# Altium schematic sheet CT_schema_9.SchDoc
size 274 x 160 mm
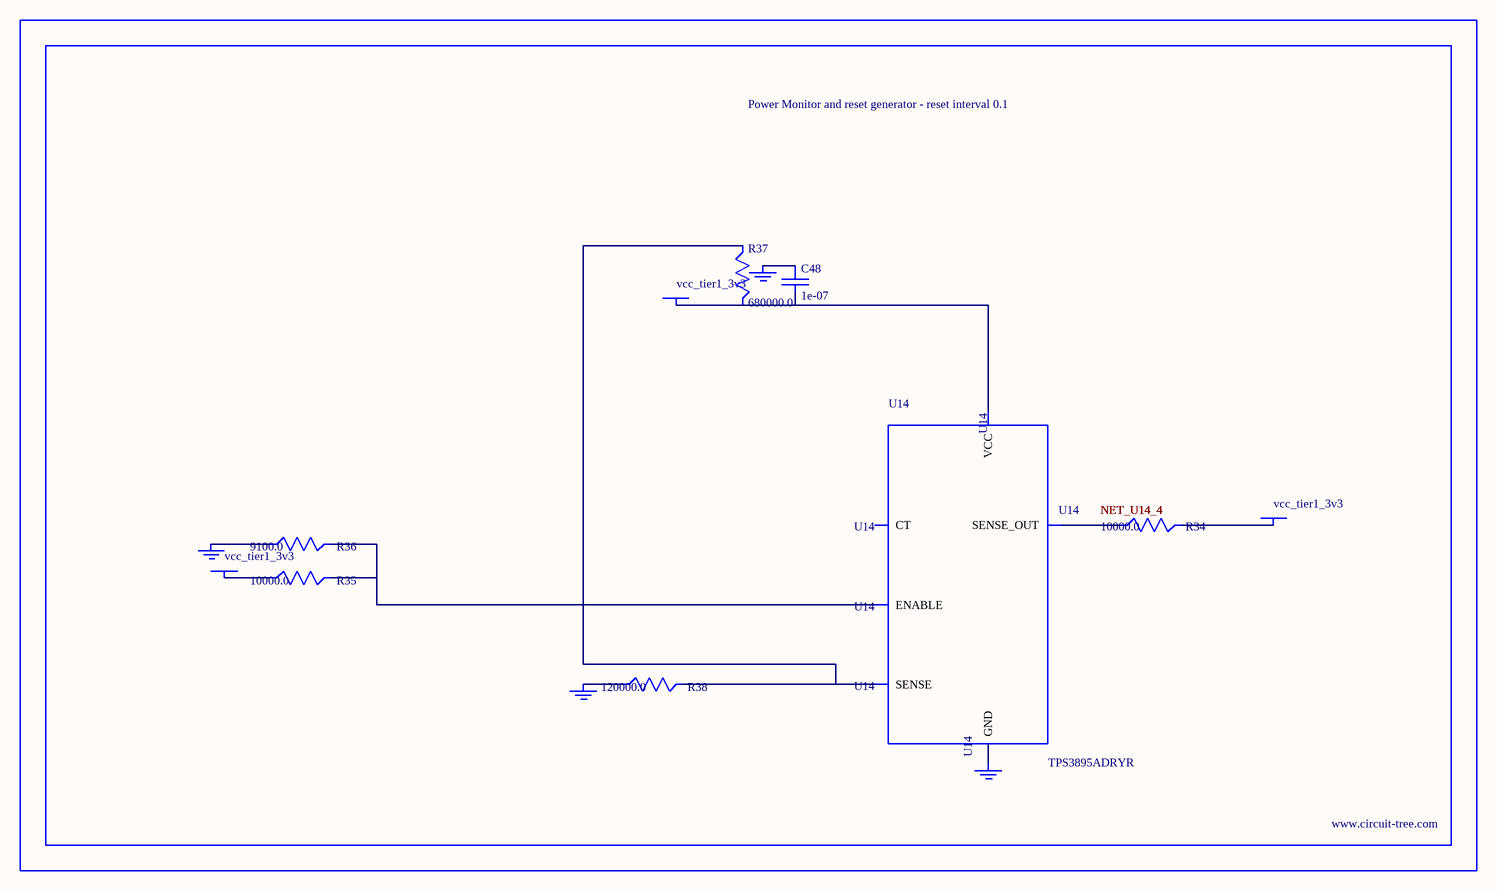
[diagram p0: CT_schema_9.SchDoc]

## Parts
BORDER8  (no value)
C48  1e-07  [C0402]
GND_INSTANCE_8_0  (no value)
GND_INSTANCE_8_1  (no value)
GND_INSTANCE_8_2  (no value)
GND_INSTANCE_8_3  (no value)
POWER_INSTANCE_8_0  vcc_tier1_3v3
POWER_INSTANCE_8_1  vcc_tier1_3v3
POWER_INSTANCE_8_2  vcc_tier1_3v3
R34  10000.0  [R0603]
R35  10000.0  [R0603]
R36  9100.0  [R0603]
R37  680000.0  [R0603]
R38  120000.0  [R0603]
U14  TPS3895ADRYR  [SON-6]

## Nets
NetC48_1: C48.1 GND_INSTANCE_8_2.0(GND)
NetC48_2: C48.2 POWER_INSTANCE_8_2.0(PWR) R37.2 U14.6(VCC)
NetGND_INSTANCE_8_0_0: GND_INSTANCE_8_0.0(GND) R36.1
NetGND_INSTANCE_8_1_0: GND_INSTANCE_8_1.0(GND) R38.1
NetGND_INSTANCE_8_3_0: GND_INSTANCE_8_3.0(GND) U14.2(GND)
NetPOWER_INSTANCE_8_0_0: POWER_INSTANCE_8_0.0(PWR) R35.1
NetPOWER_INSTANCE_8_1_0: POWER_INSTANCE_8_1.0(PWR) R34.2
NetR34_1: R34.1 U14.4(SENSE_OUT)
NetR35_2: R35.2 R36.2 U14.1(ENABLE)
NetR37_1: R37.1 R38.2 U14.3(SENSE)

Not connected (* = marked no-connect by the designer): U14 5(CT)

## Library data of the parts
BORDER8 = BORDER_PAGE8
C48 = C0402C104K3RACTU
GND_INSTANCE_8_0-GND_INSTANCE_8_3 = GND
POWER_INSTANCE_8_0-POWER_INSTANCE_8_2 = PWR
R34 R35 = RC0603JR-0710KL
R36 = RC0603JR-079K1L
R37 = RC0603JR-07680KL
R38 = RC0603JR-07120KL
